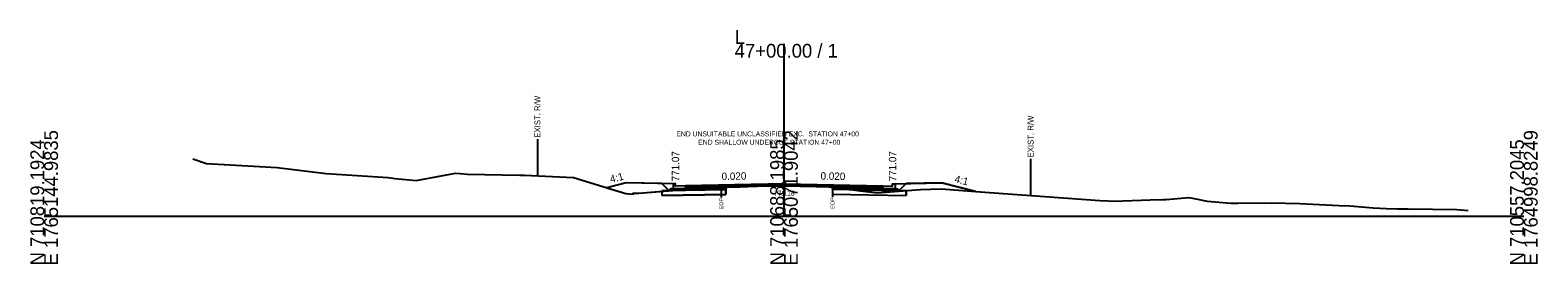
# Model space of a CAD drawing. Extents: x -26 to 5303, y -10 to 9578.
# Drawn here: x 2997.2 to 3302.8, y 6990.3 to 7037.8 of the extents above; entities that cross this region are included whole.
import ezdxf

# ---------------------------------------------------------------- set-up
doc = ezdxf.new("R2010")
doc.units = 0
for name, color, linetype in [('Default', 7, 'Continuous'), ('Exist CMT Pavement', 7, 'Continuous'), ('Exist Cross Section Cell', 7, 'Continuous'), ('Exist XS Ground Line', 7, 'Continuous'), ('Old_Level_10', 7, 'Continuous'), ('Old_Level_3', 7, 'Continuous'), ('Old_Level_4', 7, 'Continuous'), ('Prop CMT Conc Surface', 7, 'Continuous'), ('Prop CMT Concrete Structures', 7, 'Continuous'), ('Prop CMT Pvmt Course 1', 7, 'Continuous'), ('Prop CMT Pvmt Course 1 CG', 7, 'Continuous'), ('Prop CMT Pvmt Course 2', 7, 'Continuous'), ('Prop CMT Pvmt Course 3', 7, 'Continuous'), ('Prop CMT Pvmt Surface', 7, 'Continuous'), ('Prop CMT Slope Grass', 7, 'Continuous'), ('Prop CMT Subgrade Earthwork', 7, 'Continuous'), ('Prop Shade Light', 7, 'Continuous'), ('Prop XS Earthwork Shape', 7, 'Continuous'), ('Prop XS Hydro Elevations', 7, 'Continuous'), ('Prop XS SE Text', 7, 'Continuous'), ('Prop XS Side Slope Text', 7, 'Continuous'), ('Prop XS Wedging', 7, 'Continuous'), ('Scratch_Level_5', 7, 'Continuous')]:
    doc.layers.add(name, color=color, linetype=linetype)

msp = doc.modelspace()

# ---------------------------------------------------------------- linework, layer by layer
at = {"layer": 'Exist CMT Pavement'}
msp.add_lwpolyline([(3138.23, 7005.9), (3138.54, 7005.91), (3139.05, 7005.94), (3141.08, 7005.99), (3142.72, 7006.04), (3143.64, 7006.07), (3144.56, 7006.08), (3146.51, 7006.14), (3148.81, 7006.19), (3149.43, 7006.19), (3150, 7006.18), (3151.34, 7006.15), (3152.23, 7006.13), (3153.75, 7006.09), (3155.09, 7006.07), (3156.47, 7006.04), (3157.96, 7006.02), (3159.84, 7005.97)], dxfattribs=at)
at = {"layer": 'Exist Cross Section Cell'}
for p, q in [((3150, 7000), (3150, 7035)), ((3000, 7000), (3150, 7000)), ((3150, 7000), (3300, 7000))]:
    msp.add_line(p, q, dxfattribs=at)
at = {"layer": 'Exist XS Ground Line'}
msp.add_lwpolyline([(3030.13, 7011.67), (3032.9, 7010.73), (3047.25, 7009.88), (3057.2, 7008.68), (3069.77, 7007.84), (3071.17, 7007.66), (3075.39, 7007.23), (3083.42, 7008.72), (3084.31, 7008.68), (3085.79, 7008.53), (3096.46, 7008.35), (3097.39, 7008.33), (3107.32, 7007.83), (3113.3, 7006.01), (3117.92, 7004.64), (3119.41, 7004.5), (3119.45, 7004.68), (3120.55, 7004.68), (3127.96, 7005.26), (3132.39, 7005.55), (3136.62, 7005.84), (3137.29, 7005.86), (3138.54, 7005.91), (3139.05, 7005.94), (3141.08, 7005.99), (3142.72, 7006.04), (3143.64, 7006.07), (3146.51, 7006.14), (3148.81, 7006.19), (3149.43, 7006.19), (3150, 7006.18), (3151.34, 7006.15), (3151.91, 7006.14), (3152.23, 7006.13), (3153.35, 7006.11), (3155.09, 7006.07), (3156.47, 7006.04), (3157.96, 7006.02), (3158.99, 7005.99), (3159.84, 7005.94), (3165.45, 7005.12), (3168.91, 7004.76), (3177.65, 7005.44), (3181.89, 7005.54), (3190.75, 7004.9), (3202.88, 7004.02), (3214.03, 7003.2), (3215.73, 7003.11), (3216.88, 7003.08), (3224.22, 7003.29), (3226.9, 7003.37), (3227.51, 7003.41), (3232.09, 7003.81), (3233.14, 7003.58), (3235.8, 7003.04), (3240.62, 7002.67), (3242.02, 7002.61), (3248.86, 7002.71), (3254.56, 7002.55), (3262.59, 7002.17), (3264.73, 7002.07), (3267.9, 7001.84), (3269.48, 7001.69), (3272.12, 7001.57), (3274.41, 7001.5), (3276.58, 7001.5), (3286.4, 7001.35), (3288.74, 7001.12)], dxfattribs=at)
at = {"layer": 'Old_Level_10'}
for p, q in [((3100, 7015.64), (3100, 7008.24)), ((3200, 7011.63), (3200, 7004.23)), ((3137.29, 7005.86), (3137.29, 7003.81)), ((3159.84, 7005.94), (3159.84, 7003.89))]:
    msp.add_line(p, q, dxfattribs=at)
at = {"layer": 'Prop CMT Conc Surface'}
for points in [[(3128, 7006.07), (3128, 7006.57), (3127.5, 7006.57)], [(3172.01, 7006.07), (3172.01, 7006.57), (3172.51, 7006.57)], [(3130, 7006.19), (3128, 7006.07)], [(3170.01, 7006.19), (3172.01, 7006.07)]]:
    msp.add_lwpolyline(points, dxfattribs=at)
at = {"layer": 'Prop CMT Concrete Structures'}
for points in [[(3130, 7006.19), (3128, 7006.07), (3128, 7006.57), (3127.5, 7006.57)], [(3127.5, 7006.57), (3127.5, 7005.55), (3130, 7005.6)], [(3170.01, 7006.19), (3172.01, 7006.07), (3172.01, 7006.57), (3172.51, 7006.57)], [(3172.51, 7006.57), (3172.51, 7005.55), (3170.01, 7005.6)], [(3130, 7005.6), (3130, 7006.19)], [(3170.01, 7005.6), (3170.01, 7006.19)]]:
    msp.add_lwpolyline(points, dxfattribs=at)
at = {"layer": 'Prop CMT Pvmt Course 1'}
for points in [[(3150, 7006.59), (3130, 7006.19)], [(3138.23, 7006.1), (3150, 7006.34)], [(3150, 7006.34), (3150, 7006.59)], [(3150, 7006.59), (3170.01, 7006.19)], [(3150, 7006.34), (3150, 7006.34), (3150, 7006.34)], [(3159.84, 7006.14), (3150, 7006.34)], [(3130, 7006.19), (3130, 7005.94)], [(3130, 7005.94), (3138.23, 7006.1)], [(3138.23, 7006.1), (3138.23, 7006.1)], [(3170.01, 7005.94), (3159.84, 7006.14)], [(3159.84, 7006.14), (3159.84, 7006.14)], [(3170.01, 7006.19), (3170.01, 7005.94)]]:
    msp.add_lwpolyline(points, dxfattribs=at)
at = {"layer": 'Prop CMT Pvmt Course 1 CG'}
for points in [[(3130, 7005.6), (3127, 7005.54), (3126.66, 7005.2)], [(3126.66, 7005.2), (3130, 7005.27)], [(3130, 7005.27), (3130, 7005.6)], [(3170.01, 7005.6), (3173.01, 7005.54), (3173.35, 7005.2)], [(3170.01, 7005.27), (3170.01, 7005.6)], [(3173.35, 7005.2), (3170.01, 7005.27)]]:
    msp.add_lwpolyline(points, dxfattribs=at)
at = {"layer": 'Prop CMT Pvmt Course 2'}
for points in [[(3138.23, 7006.1), (3130, 7005.94)], [(3130, 7005.94), (3130, 7005.6)], [(3130, 7005.6), (3138.23, 7005.77)], [(3138.23, 7005.77), (3138.23, 7006.1)], [(3159.84, 7005.81), (3159.84, 7006.14)], [(3159.84, 7006.14), (3170.01, 7005.94)], [(3170.01, 7005.6), (3159.84, 7005.81)], [(3170.01, 7005.94), (3170.01, 7005.6)]]:
    msp.add_lwpolyline(points, dxfattribs=at)
at = {"layer": 'Prop CMT Pvmt Course 3'}
for points in [[(3138.23, 7005.77), (3130, 7005.6)], [(3130, 7005.6), (3130, 7005.27)], [(3130, 7005.27), (3138.23, 7005.43)], [(3138.23, 7005.43), (3138.23, 7005.77)], [(3159.84, 7005.81), (3170.01, 7005.6)], [(3159.84, 7005.47), (3159.84, 7005.81)], [(3170.01, 7005.27), (3159.84, 7005.47)], [(3170.01, 7005.6), (3170.01, 7005.27)]]:
    msp.add_lwpolyline(points, dxfattribs=at)
at = {"layer": 'Prop CMT Pvmt Surface'}
for points in [[(3150, 7006.59), (3130, 7006.19)], [(3150, 7006.59), (3170.01, 7006.19)]]:
    msp.add_lwpolyline(points, dxfattribs=at)
at = {"layer": 'Prop CMT Slope Grass'}
for points in [[(3127.5, 7006.57), (3118, 7006.76), (3114.08, 7005.78)], [(3172.51, 7006.57), (3182.01, 7006.76), (3188.88, 7005.04)]]:
    msp.add_lwpolyline(points, dxfattribs=at)
at = {"layer": 'Prop CMT Subgrade Earthwork'}
for p, q in [((3138.23, 7005.43), (3138.23, 7005.9)), ((3159.84, 7005.47), (3159.84, 7005.97))]:
    msp.add_line(p, q, dxfattribs=at)
for points in [[(3130, 7005.27), (3126.66, 7005.2), (3125.25, 7006.61)], [(3170.01, 7005.27), (3173.35, 7005.2), (3174.75, 7006.61)], [(3138.23, 7005.43), (3130, 7005.27)], [(3159.84, 7005.47), (3170.01, 7005.27)]]:
    msp.add_lwpolyline(points, dxfattribs=at)
at = {"layer": 'Prop Shade Light'}
for p, q in [((3125.44, 7005.16), (3125.25, 7005.15)), ((3125.25, 7005.15), (3125.25, 7004.17)), ((3125.25, 7005.15), (3125.25, 7004.17)), ((3125.25, 7004.17), (3138.23, 7004.43)), ((3126.63, 7005.23), (3125.44, 7005.16)), ((3126.66, 7005.2), (3126.63, 7005.23)), ((3126.81, 7005.21), (3126.66, 7005.2)), ((3128.25, 7005.23), (3126.81, 7005.21)), ((3129.69, 7005.26), (3128.25, 7005.23)), ((3130, 7005.27), (3129.69, 7005.26)), ((3131.13, 7005.29), (3130, 7005.27)), ((3135.46, 7005.38), (3134.02, 7005.35)), ((3136.91, 7005.41), (3135.46, 7005.38)), ((3138.23, 7005.43), (3136.91, 7005.41)), ((3138.23, 7005.47), (3138.23, 7004.43)), ((3138.23, 7004.43), (3138.23, 7005.43)), ((3159.84, 7005.51), (3159.84, 7004.47)), ((3160.23, 7005.46), (3159.84, 7005.47)), ((3159.84, 7005.47), (3159.84, 7004.47)), ((3159.84, 7004.47), (3174.75, 7004.17)), ((3161.61, 7005.44), (3160.23, 7005.46)), ((3163, 7005.41), (3161.61, 7005.44)), ((3163.54, 7005.4), (3163, 7005.41)), ((3174.75, 7005.21), (3168.91, 7004.76)), ((3174.75, 7005.21), (3174.75, 7004.17)), ((3174.75, 7004.17), (3174.75, 7005.21))]:
    msp.add_line(p, q, dxfattribs=at)
for points in [[(3138.23, 7004.43), (3125.25, 7004.17)], [(3134.02, 7005.35), (3132.58, 7005.32), (3131.13, 7005.29)], [(3159.84, 7004.47), (3174.75, 7004.17)], [(3168.91, 7004.76), (3165.45, 7005.12), (3163.54, 7005.4)]]:
    msp.add_lwpolyline(points, dxfattribs=at)
at = {"layer": 'Prop XS Earthwork Shape'}
for p, q in [((3126.63, 7005.23), (3125.25, 7006.61)), ((3114.08, 7005.78), (3117.92, 7004.64)), ((3126.66, 7005.2), (3126.63, 7005.23)), ((3126.81, 7005.21), (3126.66, 7005.2)), ((3127.48, 7005.22), (3126.81, 7005.21))]:
    msp.add_line(p, q, dxfattribs=at)
for points in [[(3125.25, 7006.61), (3118, 7006.76), (3114.08, 7005.78)], [(3117.92, 7004.64), (3119.41, 7004.5), (3119.45, 7004.68), (3120.55, 7004.68), (3127.48, 7005.22)]]:
    msp.add_lwpolyline(points, dxfattribs=at)
for points in [[(3163.54, 7005.4), (3165.45, 7005.12), (3168.91, 7004.76), (3177.65, 7005.44), (3181.89, 7005.54), (3188.88, 7005.04), (3182.01, 7006.76), (3174.75, 7006.61), (3173.35, 7005.2), (3170.01, 7005.27)], [(3138.23, 7005.43), (3130, 7005.27), (3126.66, 7005.2), (3126.63, 7005.23), (3130.18, 7005.45), (3137.29, 7005.86), (3138.23, 7005.9)], [(3159.84, 7005.94), (3159.84, 7005.97), (3158.99, 7005.99)], [(3158.99, 7005.99), (3159.84, 7005.97), (3159.84, 7005.94)], [(3159.84, 7005.94), (3163.54, 7005.4), (3159.84, 7005.47)]]:
    msp.add_lwpolyline(points, close=True, dxfattribs=at)
at = {"layer": 'Prop XS Wedging'}
msp.add_lwpolyline([(3138.54, 7005.91), (3138.54, 7006.11), (3139.05, 7006.12), (3141.08, 7006.16), (3142.72, 7006.19), (3143.64, 7006.21), (3144.56, 7006.23), (3146.51, 7006.27), (3148.81, 7006.31), (3149.43, 7006.32), (3150, 7006.34), (3151.34, 7006.31), (3152.23, 7006.29), (3153.75, 7006.26), (3155.09, 7006.23), (3156.47, 7006.21), (3157.96, 7006.18), (3158.99, 7006.16), (3159.84, 7006.14), (3159.84, 7005.94), (3158.99, 7005.99), (3157.96, 7006.02), (3156.47, 7006.04), (3155.09, 7006.07), (3153.75, 7006.09), (3152.23, 7006.13), (3151.34, 7006.15), (3150, 7006.18), (3149.43, 7006.19), (3148.81, 7006.19), (3146.51, 7006.14), (3144.56, 7006.08), (3143.64, 7006.07), (3142.72, 7006.04), (3141.08, 7005.99), (3139.05, 7005.94)], close=True, dxfattribs=at)
at = {"layer": 'Scratch_Level_5'}
for p, q in [((3126.81, 7005.21), (3126.85, 7005.25)), ((3128.25, 7005.23), (3128.35, 7005.34)), ((3129.69, 7005.26), (3129.86, 7005.43)), ((3131.13, 7005.29), (3131.36, 7005.52)), ((3132.58, 7005.32), (3132.86, 7005.61)), ((3134.02, 7005.35), (3134.36, 7005.69)), ((3135.46, 7005.38), (3135.87, 7005.78)), ((3136.91, 7005.41), (3137.37, 7005.87)), ((3160.23, 7005.46), (3160.59, 7005.83)), ((3161.61, 7005.44), (3161.83, 7005.65)), ((3163, 7005.41), (3163.06, 7005.47))]:
    msp.add_line(p, q, dxfattribs=at)

# ---------------------------------------------------------------- texts
at = {"layer": 'Default'}
msp.add_text('-', height=0.0001, dxfattribs=at).set_placement((3000, 7000))
at = {"layer": 'Exist Cross Section Cell'}
for s, p in [('L', (3140, 7035)), ('47+00.00 / 1', (3140, 7032.2))]:
    msp.add_text(s, height=2.8, dxfattribs=at).set_placement(p)
for s, p in [('N 710819.1924', (3000, 6990)), ('E 1765144.9835', (3002.8, 6990)), ('N 710688.1985', (3150, 6990)), ('E 1765071.9042', (3152.8, 6990)), ('N 710557.2045', (3300, 6990)), ('E 1764998.8249', (3302.8, 6990))]:
    msp.add_text(s, height=2.8, rotation=90, dxfattribs=at).set_placement(p)
at = {"layer": 'Old_Level_10'}
for s, height, p in [('EXIST. R/W', 1.181, (3100.59, 7015.94)), ('EXIST. R/W', 1.181, (3200.59, 7011.93)), ('EOP', 0.787, (3137.68, 7001.42)), ('EOP', 0.787, (3160.23, 7001.49))]:
    msp.add_text(s, height=height, rotation=90, dxfattribs=at).set_placement(p)
at = {"layer": 'Old_Level_3'}
msp.add_text('771.18', height=1, dxfattribs=at).set_placement((3147.95, 7004.18))
at = {"layer": 'Old_Level_4'}
msp.add_text('END SHALLOW UNDERCUT STATION 47+00', height=1, dxfattribs=at).set_placement((3132.61, 7014.52))
at = {"layer": 'Prop XS Hydro Elevations'}
for p in [(3128.75, 7007.07), (3172.76, 7007.07)]:
    msp.add_text('771.07', height=1.5, rotation=90, dxfattribs=at).set_placement(p)
at = {"layer": 'Prop XS SE Text'}
for rotation, p in [(1.1458, (3137.36, 7007.33)), (358.8542, (3157.4, 7007.44))]:
    msp.add_text('0.020', height=1.5, rotation=rotation, dxfattribs=at).set_placement(p)
at = {"layer": 'Prop XS Side Slope Text'}
for rotation, p in [(14.0362, (3114.91, 7006.76)), (345.9638, (3184.47, 7006.91))]:
    msp.add_text('4:1', height=1.5, rotation=rotation, dxfattribs=at).set_placement(p)
at = {"layer": 'Scratch_Level_5'}
msp.add_text('END UNSUITABLE UNCLASSIFIED EXC.  STATION 47+00', height=1, dxfattribs=at).set_placement((3128.16, 7016.21))

doc.saveas('drawing.dxf')
